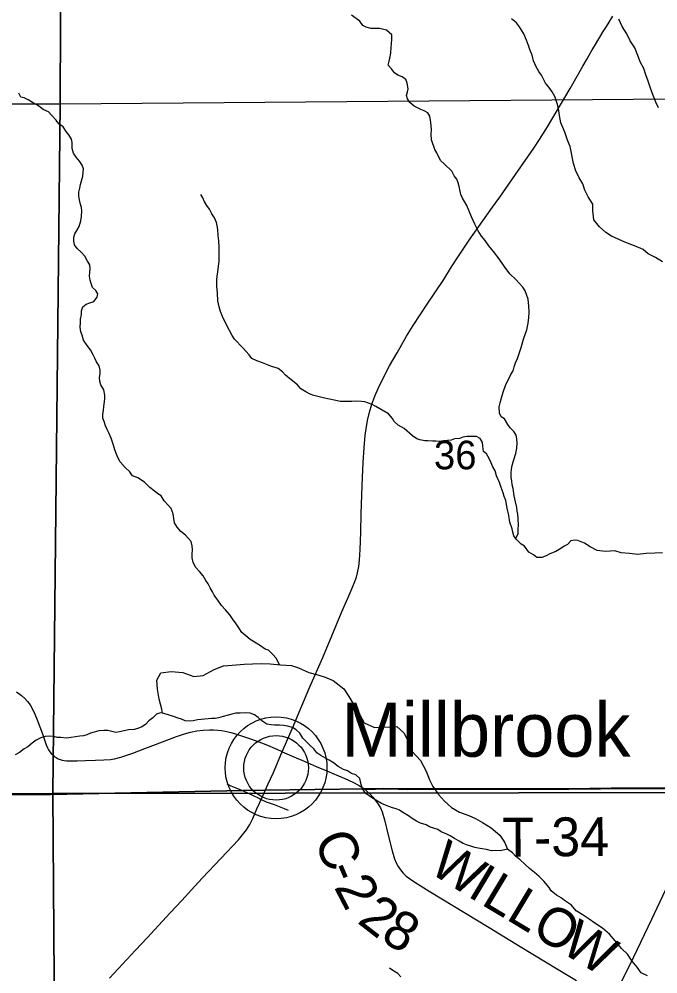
# Model space of a CAD drawing. Extents: x 0 to 34, y 0 to 22.
# Drawn here: x 4.694 to 5.628, y 15 to 16.396 of the extents above; entities that cross this region are included whole.
import ezdxf

# ---------------------------------------------------------------- set-up
doc = ezdxf.new("R2010")
doc.units = 0
for name, color, linetype in [('GM_X_County_Road', 7, 'Continuous'), ('GM_X_County_Road_Text', 7, 'Continuous'), ('GM_X_Minor_River', 7, 'Continuous'), ('GM_X_Section', 7, 'Continuous'), ('GM_X_Section_Text', 7, 'Continuous'), ('GM_X_State_Route', 7, 'Continuous'), ('GM_X_Township_Road', 7, 'Continuous'), ('GM_X_Township_Road_Text', 7, 'Continuous'), ('GM_X_Unincorporated', 7, 'Continuous'), ('GM_X_Unincorporated_Location', 7, 'Continuous'), ('GM_X_Unincorporated_Text', 7, 'Continuous')]:
    doc.layers.add(name, color=color, linetype=linetype)

msp = doc.modelspace()

# ---------------------------------------------------------------- linework, layer by layer
at = {"layer": 'GM_X_County_Road'}
msp.add_line((5.0478, 15.2549), (5.0536, 15.2677), dxfattribs=at)
for points in [[(5.0786, 15.3245), (5.0863, 15.3426), (5.0948, 15.3626), (5.1034, 15.3825), (5.119, 15.4195), (5.1376, 15.4624), (5.1512, 15.4939), (5.1653, 15.528), (5.1779, 15.5567), (5.1836, 15.5708), (5.1869, 15.5797), (5.1886, 15.586), (5.1903, 15.5953), (5.1914, 15.6046), (5.1923, 15.6201), (5.1932, 15.645), (5.194, 15.6729), (5.1954, 15.7132), (5.196, 15.7256), (5.1968, 15.7472), (5.198, 15.7689), (5.1999, 15.7874), (5.2011, 15.7966), (5.2033, 15.8088), (5.2062, 15.8208), (5.2096, 15.8327), (5.2138, 15.8443), (5.2186, 15.8557), (5.2254, 15.8696), (5.2355, 15.8888), (5.2463, 15.9077), (5.2603, 15.9318), (5.27, 15.9478), (5.2903, 15.9789), (5.3025, 15.997), (5.3146, 16.015), (5.3261, 16.0335), (5.3361, 16.0492), (5.3517, 16.0724), (5.3857, 16.1206), (5.3964, 16.1354), (5.4054, 16.148), (5.4196, 16.1684), (5.4461, 16.2067), (5.4545, 16.2197), (5.466, 16.2382), (5.485, 16.2702), (5.4994, 16.2942), (5.5181, 16.3265), (5.5241, 16.3373), (5.5271, 16.3426), (5.5316, 16.3506), (5.5347, 16.356), (5.5426, 16.3693), (5.5475, 16.3772), (5.5525, 16.3849), (5.5618, 16.4)], [(4.6902, 15.4122), (4.6975, 15.4066), (4.7021, 15.4025), (4.7063, 15.3981), (4.7099, 15.3932), (4.713, 15.3879), (4.717, 15.3796), (4.7204, 15.371), (4.7279, 15.3505), (4.7336, 15.3348), (4.7355, 15.3301), (4.737, 15.3273), (4.7387, 15.3246), (4.7407, 15.3221), (4.7429, 15.3198), (4.7453, 15.3177), (4.748, 15.3159), (4.7508, 15.3144), (4.7538, 15.3132), (4.7568, 15.3124), (4.7599, 15.3118), (4.7631, 15.3114), (4.7694, 15.3112), (4.7788, 15.3114), (4.7909, 15.3118), (4.8056, 15.312), (4.8179, 15.3125), (4.8273, 15.3134), (4.8335, 15.3144), (4.8426, 15.3165), (4.8486, 15.3184), (4.8602, 15.3227), (4.8776, 15.3294), (4.8891, 15.3338), (4.9239, 15.3469), (4.9357, 15.3508), (4.9446, 15.3532), (4.9536, 15.355), (4.9628, 15.3561), (4.9721, 15.3566), (4.9782, 15.3565), (4.9844, 15.3563), (4.9898, 15.3557), (4.9949, 15.3547), (4.9995, 15.3536), (5.0034, 15.3525), (5.0088, 15.351), (5.0203, 15.3475), (5.032, 15.3435), (5.0495, 15.3371), (5.0601, 15.3328), (5.0645, 15.3308), (5.0706, 15.3282), (5.0778, 15.3248), (5.0786, 15.3245)], [(5.0536, 15.2677), (5.0581, 15.2774), (5.0655, 15.2944), (5.0766, 15.3198), (5.0786, 15.3245)], [(5.0786, 15.3245), (5.0887, 15.3201), (5.0988, 15.3158), (5.1071, 15.3123), (5.1195, 15.3068), (5.128, 15.3032), (5.1365, 15.2994), (5.1425, 15.2969), (5.1513, 15.2932), (5.1702, 15.2853), (5.1816, 15.2801), (5.1909, 15.2751), (5.1951, 15.2725), (5.199, 15.2698)], [(5.199, 15.2698), (5.202, 15.2671), (5.2069, 15.2624), (5.211, 15.258), (5.215, 15.2532), (5.2187, 15.2481), (5.2204, 15.2455), (5.2219, 15.2426), (5.2243, 15.2368), (5.2278, 15.2248), (5.2339, 15.2007), (5.2392, 15.1796), (5.2428, 15.1678), (5.245, 15.1621), (5.2479, 15.1567), (5.2514, 15.1517), (5.2554, 15.147), (5.2598, 15.1429), (5.2647, 15.1391), (5.2723, 15.1339), (5.2934, 15.1208), (5.3811, 15.0675), (5.4262, 15.04), (5.4632, 15.0172), (5.4792, 15.0075), (5.5085, 14.99)], [(4.826, 14.9937), (4.8642, 15.0345), (4.8811, 15.0527), (4.9148, 15.0892), (4.9318, 15.1073), (4.9508, 15.1278), (4.9617, 15.1401), (4.9885, 15.1687), (5.0145, 15.1958), (5.0206, 15.2029), (5.0262, 15.2105), (5.0311, 15.2184), (5.0353, 15.2268), (5.0415, 15.241), (5.0452, 15.2495), (5.0478, 15.2549)]]:
    msp.add_lwpolyline(points, dxfattribs=at)
at = {"layer": 'GM_X_Minor_River'}
for points in [[(5.2426, 16.3169), (5.2381, 16.323), (5.2335, 16.3283), (5.2346, 16.334), (5.2357, 16.3386), (5.2372, 16.3458), (5.2376, 16.3546), (5.2383, 16.3595), (5.2387, 16.3663), (5.2387, 16.3724), (5.231, 16.3793), (5.2207, 16.3819), (5.2078, 16.3819), (5.2013, 16.3835), (5.1963, 16.3861), (5.1917, 16.3926), (5.1799, 16.4014)], [(5.5041, 16.1842), (5.5005, 16.2042), (5.4994, 16.2095), (5.4955, 16.2183), (5.4917, 16.2301), (5.4859, 16.2441), (5.484, 16.2544), (5.4824, 16.2647), (5.4805, 16.2719), (5.477, 16.2822), (5.4728, 16.2894), (5.4682, 16.2962), (5.4633, 16.3019), (5.4602, 16.3077), (5.4575, 16.3137), (5.4537, 16.3187), (5.4498, 16.3255), (5.4456, 16.3347), (5.4437, 16.343), (5.4406, 16.351), (5.4383, 16.3571), (5.4356, 16.3647), (5.4318, 16.3742), (5.4253, 16.3841), (5.4207, 16.3898), (5.4134, 16.3959)], [(5.6284, 16.2656), (5.6247, 16.2743), (5.6206, 16.2838), (5.6168, 16.2945), (5.6135, 16.3047), (5.6101, 16.3142), (5.6071, 16.3233), (5.6015, 16.3329), (5.5981, 16.3424), (5.594, 16.3534), (5.5872, 16.3637), (5.582, 16.3739), (5.5756, 16.3846), (5.5707, 16.3956)], [(5.4201, 15.6361), (5.4232, 15.6437), (5.4232, 15.6506), (5.4236, 15.6551), (5.4232, 15.6654), (5.4228, 15.6719), (5.422, 15.6764), (5.4212, 15.6818), (5.4193, 15.6897), (5.4174, 15.6985), (5.4158, 15.7091), (5.4147, 15.7145), (5.4139, 15.7206), (5.4131, 15.7255), (5.4131, 15.7316), (5.4135, 15.7377), (5.4146, 15.743), (5.4161, 15.7483), (5.4199, 15.7605), (5.4214, 15.7685), (5.4218, 15.7757), (5.4214, 15.7818), (5.4202, 15.7871), (5.4171, 15.7928), (5.4118, 15.7981), (5.4083, 15.8027), (5.4034, 15.8111), (5.3984, 15.8141), (5.3961, 15.8194), (5.3957, 15.8289), (5.3968, 15.8346), (5.3991, 15.8419), (5.4014, 15.8502), (5.4055, 15.8613), (5.4093, 15.8689), (5.4124, 15.8761), (5.4158, 15.8814), (5.4177, 15.8871), (5.4196, 15.8932), (5.4222, 15.8993), (5.4249, 15.9065), (5.4279, 15.9156), (5.4309, 15.9278), (5.434, 15.9358), (5.4359, 15.9415), (5.437, 15.946), (5.4378, 15.951), (5.4389, 15.9593), (5.4392, 15.9673), (5.4388, 15.9761), (5.4381, 15.986), (5.4338, 15.9985), (5.4304, 16.0038), (5.425, 16.0095), (5.4201, 16.0149), (5.4116, 16.0225), (5.404, 16.0328), (5.3956, 16.0449), (5.3871, 16.056), (5.3806, 16.0639), (5.3753, 16.0719), (5.3699, 16.0784), (5.3649, 16.086), (5.3599, 16.0959), (5.355, 16.1066), (5.3519, 16.1149), (5.3484, 16.1229), (5.345, 16.129), (5.3419, 16.1339), (5.3396, 16.1393), (5.3385, 16.1442), (5.3369, 16.1507), (5.3358, 16.1564), (5.3335, 16.1617), (5.33, 16.1666), (5.3262, 16.1731), (5.3151, 16.1841), (5.3101, 16.1883), (5.3074, 16.1937), (5.3044, 16.2001), (5.3013, 16.2047), (5.2967, 16.2191), (5.2963, 16.2275), (5.2967, 16.234), (5.2959, 16.2442), (5.2943, 16.2534), (5.2913, 16.2583), (5.2859, 16.2614), (5.2809, 16.2633), (5.276, 16.2659), (5.2714, 16.2682), (5.2649, 16.2735), (5.2614, 16.2789), (5.2603, 16.2838), (5.2618, 16.2891), (5.2625, 16.2937), (5.261, 16.3017), (5.2591, 16.3074), (5.2537, 16.3112), (5.2476, 16.3135), (5.2426, 16.3169)], [(4.7862, 16.1818), (4.7819, 16.1879), (4.777, 16.1936), (4.7735, 16.1997), (4.7716, 16.2065), (4.7716, 16.2149), (4.7704, 16.2198), (4.7666, 16.2263), (4.7624, 16.2312), (4.7582, 16.2381), (4.7517, 16.2426), (4.7482, 16.248), (4.7417, 16.2544), (4.7367, 16.2598), (4.7291, 16.2632), (4.7207, 16.2697), (4.7134, 16.2735), (4.7073, 16.2773), (4.7012, 16.2803), (4.6962, 16.2815), (4.6936, 16.2872)], [(4.952, 15.5938), (4.9482, 15.6014), (4.947, 15.6079), (4.947, 15.6132), (4.9474, 15.62), (4.947, 15.6257), (4.9451, 15.6318), (4.937, 15.6413), (4.9302, 15.6463), (4.9248, 15.6528), (4.921, 15.6592), (4.9202, 15.6653), (4.919, 15.6725), (4.916, 15.6801), (4.911, 15.6855), (4.906, 15.6912), (4.9014, 15.6984), (4.8964, 15.7014), (4.8911, 15.706), (4.885, 15.711), (4.8773, 15.7186), (4.8674, 15.725), (4.8597, 15.7277), (4.8555, 15.7338), (4.849, 15.7399), (4.8414, 15.7483), (4.8383, 15.7547), (4.836, 15.7597), (4.8337, 15.7661), (4.8318, 15.7726), (4.8283, 15.7829), (4.8252, 15.7905), (4.8226, 15.7958), (4.8203, 15.8011), (4.818, 15.8072), (4.816, 15.8122), (4.8164, 15.8179), (4.8172, 15.8232), (4.8175, 15.8293), (4.8187, 15.8361), (4.819, 15.841), (4.819, 15.846), (4.8175, 15.8536), (4.8132, 15.8608), (4.8117, 15.8661), (4.8113, 15.8715), (4.8124, 15.8768), (4.8124, 15.8825), (4.8109, 15.8886), (4.8071, 15.8947), (4.8044, 15.9), (4.8021, 15.9049), (4.7982, 15.9118), (4.7933, 15.9186), (4.7879, 15.9262), (4.786, 15.9335), (4.7841, 15.9384), (4.7833, 15.9453), (4.7836, 15.9517), (4.7836, 15.9567), (4.7848, 15.9639), (4.7851, 15.9692), (4.787, 15.9749), (4.792, 15.9787), (4.7973, 15.9806), (4.803, 15.9825), (4.808, 15.989), (4.8087, 15.9939), (4.8061, 15.9989), (4.8011, 16.0034), (4.7992, 16.0091), (4.7976, 16.0141), (4.7965, 16.0198), (4.7972, 16.0255), (4.7976, 16.0308), (4.7972, 16.0365), (4.7937, 16.0418), (4.7899, 16.0491), (4.7845, 16.0548), (4.7788, 16.0601), (4.775, 16.0654), (4.7738, 16.0708), (4.7738, 16.0765), (4.7753, 16.0814), (4.7784, 16.0867), (4.7814, 16.0924), (4.7841, 16.1004), (4.7852, 16.1069), (4.7855, 16.1152), (4.7848, 16.1202), (4.7832, 16.1263), (4.7821, 16.1312), (4.7813, 16.1365), (4.7813, 16.1426), (4.7824, 16.1483), (4.7835, 16.1536), (4.7851, 16.1593), (4.787, 16.1658), (4.7873, 16.1715), (4.7881, 16.1765), (4.7862, 16.1818)], [(5.6344, 16.0405), (5.6242, 16.047), (5.6136, 16.0524), (5.6061, 16.0589), (5.5936, 16.0642), (5.5793, 16.0692), (5.5695, 16.0738), (5.56, 16.0784), (5.5517, 16.0834), (5.5423, 16.0918), (5.534, 16.1021), (5.5326, 16.115), (5.5326, 16.1249), (5.5258, 16.1359), (5.5206, 16.1454), (5.518, 16.1545), (5.5127, 16.1633), (5.5078, 16.1736), (5.5041, 16.1842)], [(4.9864, 16.0619), (4.9856, 16.0714), (4.9848, 16.0794), (4.9844, 16.0877), (4.9833, 16.0935), (4.9825, 16.098), (4.9794, 16.1052), (4.9756, 16.1109), (4.9722, 16.1178), (4.9683, 16.1231), (4.9649, 16.1284), (4.9626, 16.1342), (4.9595, 16.1391)], [(5.5107, 15.6332), (5.5057, 15.6338), (5.5003, 15.6327), (5.4954, 15.6277), (5.4908, 15.6251), (5.4855, 15.6216), (5.4782, 15.6171), (5.4698, 15.6137), (5.4641, 15.611), (5.4577, 15.6087), (5.4504, 15.6087), (5.4458, 15.6122), (5.4389, 15.6163), (5.4324, 15.6251), (5.4278, 15.6278), (5.4206, 15.6354), (5.4171, 15.6403), (5.4156, 15.6453), (5.4144, 15.6506), (5.4114, 15.6601), (5.4098, 15.67), (5.4071, 15.6806), (5.4052, 15.6917), (5.4029, 15.6977), (5.4013, 15.7031), (5.3983, 15.7107), (5.3959, 15.7183), (5.3917, 15.7278), (5.3898, 15.7354), (5.3864, 15.7411), (5.3833, 15.7476), (5.381, 15.7533), (5.3772, 15.7601), (5.3726, 15.7635), (5.3718, 15.7712), (5.371, 15.7765), (5.3679, 15.7822), (5.3626, 15.7852), (5.3481, 15.7852), (5.3427, 15.7845), (5.3374, 15.7826), (5.3305, 15.7818), (5.3252, 15.7799), (5.3141, 15.7788), (5.3084, 15.778), (5.3031, 15.7784), (5.2985, 15.7784), (5.2912, 15.7788), (5.2867, 15.7792), (5.2798, 15.7803), (5.2752, 15.7819), (5.2691, 15.7864), (5.2568, 15.7971), (5.2481, 15.802), (5.2423, 15.8073), (5.2396, 15.8119), (5.2339, 15.8184), (5.2243, 15.8237), (5.2152, 15.829), (5.2098, 15.8321), (5.1991, 15.8359), (5.1942, 15.8367), (5.1858, 15.837), (5.1804, 15.8367), (5.1759, 15.8363), (5.1705, 15.8363), (5.1633, 15.8367), (5.1568, 15.8378), (5.1381, 15.842), (5.1247, 15.8451), (5.1193, 15.847), (5.1132, 15.8508), (5.1056, 15.855), (5.1006, 15.8607), (5.0914, 15.8683), (5.0834, 15.8751), (5.0788, 15.8797), (5.0727, 15.8846), (5.062, 15.8881), (5.0544, 15.8911), (5.0498, 15.893), (5.0414, 15.8961), (5.0341, 15.8995), (5.0303, 15.9048), (5.0207, 15.9151), (5.0085, 15.9276), (5.0054, 15.933), (4.9974, 15.9474), (4.9912, 15.9607), (4.9882, 15.9683), (4.9862, 15.9748), (4.9843, 15.9836), (4.9839, 15.995), (4.9827, 16.0052), (4.9831, 16.0144), (4.9835, 16.0197), (4.9842, 16.0261), (4.9853, 16.0345), (4.9861, 16.0414), (4.9864, 16.0474), (4.9864, 16.0619)], [(5.6343, 15.6152), (5.6229, 15.6148), (5.6104, 15.6141), (5.5983, 15.6127), (5.5859, 15.6143), (5.5741, 15.6155), (5.5647, 15.6182), (5.5511, 15.6171), (5.539, 15.6187), (5.5284, 15.624), (5.5201, 15.6294), (5.5107, 15.6332)], [(5.0745, 15.4516), (5.0703, 15.4606), (5.0641, 15.4671), (5.0584, 15.4728), (5.0534, 15.4743), (5.0454, 15.4804), (5.0317, 15.4888), (5.0252, 15.4938), (5.0194, 15.4987), (5.0148, 15.5059), (5.011, 15.5113), (5.0056, 15.5189), (5.0018, 15.5249), (4.9953, 15.5318), (4.9896, 15.5383), (4.9842, 15.5459), (4.9792, 15.5535), (4.9765, 15.5584), (4.9731, 15.5641), (4.97, 15.5698), (4.967, 15.5748), (4.9631, 15.5816), (4.9574, 15.5881), (4.952, 15.5938)], [(4.9033, 15.3809), (4.9025, 15.3867), (4.8987, 15.4015), (4.896, 15.4159), (4.8951, 15.4292), (4.9008, 15.4399), (4.9163, 15.4418), (4.9334, 15.4403), (4.9493, 15.4347), (4.9629, 15.4359), (4.9788, 15.445), (4.9928, 15.45), (5.0053, 15.4512), (5.0227, 15.4524), (5.0352, 15.4532), (5.0485, 15.4536), (5.061, 15.4529), (5.0761, 15.4514), (5.092, 15.4504), (5.1023, 15.4474), (5.1174, 15.4402), (5.1307, 15.4372), (5.141, 15.4334), (5.1527, 15.4285), (5.1687, 15.4164), (5.1759, 15.4055), (5.1831, 15.3933), (5.1896, 15.3827), (5.1984, 15.3668), (5.2132, 15.36), (5.2261, 15.3608), (5.2363, 15.3605), (5.2461, 15.3613), (5.256, 15.3522), (5.2644, 15.3363), (5.2686, 15.3249), (5.2804, 15.3117), (5.2888, 15.2962), (5.2938, 15.2833), (5.2984, 15.2738), (5.3068, 15.2621), (5.3159, 15.2522), (5.3258, 15.2428), (5.3375, 15.2363), (5.3512, 15.2311), (5.361, 15.2269), (5.3713, 15.2209), (5.3838, 15.2133), (5.3967, 15.2024), (5.4032, 15.1925), (5.4077, 15.1823)], [(5.4077, 15.1823), (5.3968, 15.1798), (5.3904, 15.1802), (5.3842, 15.1795), (5.377, 15.1817), (5.3709, 15.1825), (5.3648, 15.1837), (5.3598, 15.1848), (5.3541, 15.1863), (5.348, 15.1886), (5.343, 15.1905), (5.3373, 15.1936), (5.3304, 15.1977), (5.3239, 15.2015), (5.3189, 15.2042), (5.3109, 15.2076), (5.3059, 15.2107), (5.2998, 15.213), (5.2937, 15.2149), (5.2888, 15.2175), (5.2807, 15.2202), (5.2746, 15.2229), (5.2685, 15.2271), (5.2632, 15.2309), (5.2547, 15.2358), (5.2498, 15.2389), (5.2448, 15.2411), (5.2395, 15.2427), (5.2341, 15.2446), (5.2292, 15.2465), (5.2234, 15.2488), (5.2154, 15.2537), (5.2089, 15.2575), (5.2009, 15.2636), (5.1959, 15.2704), (5.194, 15.2765), (5.1917, 15.2853), (5.1859, 15.2906), (5.1798, 15.2929), (5.1741, 15.2967), (5.168, 15.2986), (5.1603, 15.3032), (5.1534, 15.3081), (5.1473, 15.3123), (5.1416, 15.3153), (5.1347, 15.3192), (5.129, 15.323), (5.1248, 15.3287), (5.119, 15.334), (5.1137, 15.3389), (5.1087, 15.3446), (5.1041, 15.3515), (5.0988, 15.3568), (5.0934, 15.3602), (5.0861, 15.3618), (5.0804, 15.3629), (5.0743, 15.3633), (5.0674, 15.3633), (5.0625, 15.3637), (5.056, 15.3648), (5.0487, 15.3698), (5.0434, 15.3747), (5.038, 15.3785), (5.0315, 15.3808), (5.0243, 15.3812), (5.017, 15.3808), (5.0105, 15.3808), (5.0048, 15.3793), (4.9995, 15.3782), (4.9922, 15.3759), (4.9854, 15.374), (4.9804, 15.3729), (4.9751, 15.3729), (4.9602, 15.3717), (4.9545, 15.371), (4.9484, 15.3698), (4.9423, 15.3691), (4.9365, 15.3698), (4.9312, 15.3721), (4.9262, 15.3736), (4.9197, 15.3763), (4.9117, 15.3786), (4.9056, 15.3805), (4.9006, 15.3813), (4.8945, 15.3797), (4.8892, 15.374), (4.8835, 15.3695), (4.8785, 15.3642), (4.8732, 15.3611), (4.8675, 15.3585), (4.8621, 15.357), (4.8538, 15.3566), (4.8473, 15.3551), (4.8404, 15.3535), (4.8351, 15.3528), (4.8293, 15.3539), (4.8236, 15.3555), (4.8179, 15.3555), (4.8106, 15.3551), (4.8034, 15.3532), (4.7984, 15.3517)], [(4.7984, 15.3517), (4.7927, 15.3494), (4.7878, 15.3479), (4.7828, 15.3475), (4.7698, 15.3456), (4.7633, 15.3445), (4.7546, 15.3456), (4.7496, 15.3456), (4.7446, 15.3467), (4.7378, 15.3471), (4.732, 15.3468), (4.7256, 15.3449), (4.7187, 15.3414), (4.713, 15.3373), (4.7065, 15.3319), (4.7012, 15.3289), (4.6943, 15.3236), (4.6882, 15.3198)], [(5.5079, 15.0921), (5.5012, 15.1003), (5.4913, 15.1071), (5.4863, 15.111), (5.4794, 15.1151), (5.4718, 15.1212), (5.4687, 15.1262), (5.4611, 15.1353), (5.4538, 15.1422), (5.4473, 15.1479), (5.44, 15.1539), (5.4331, 15.1604), (5.4259, 15.1669), (5.4201, 15.1715), (5.4152, 15.1768), (5.4077, 15.1823)], [(5.6126, 14.9969), (5.6031, 15.0015), (5.5974, 15.0098), (5.5902, 15.0186), (5.583, 15.0285), (5.5743, 15.0369), (5.5652, 15.0483), (5.5568, 15.0578), (5.5466, 15.0666), (5.5356, 15.0742), (5.5269, 15.0799), (5.5167, 15.0864), (5.5079, 15.0921)], [(5.2519, 14.9955), (5.2473, 15.0004), (5.2416, 15.0039), (5.2354, 15.008)]]:
    msp.add_lwpolyline(points, dxfattribs=at)
at = {"layer": 'GM_X_Section'}
for points in [[(4.7564, 16.8709), (4.754, 16.2718), (5.7718, 16.2797), (5.7724, 17.2281), (5.7727, 17.3042), (4.804, 17.2765), (4.804, 16.8709)], [(3.7435, 16.8709), (3.7413, 16.2718), (4.754, 16.2718), (4.7564, 16.8709)], [(5.7718, 16.2797), (5.7699, 16.2149), (5.7637, 15.2651), (4.743, 15.2637), (4.754, 16.2718)], [(3.7413, 16.2718), (4.754, 16.2718), (4.743, 15.2637), (3.7425, 15.2596), (3.7269, 15.2595)], [(3.7425, 15.2596), (4.743, 15.2637), (4.7506, 14.2503), (4.2965, 14.2473), (3.7447, 14.2621)], [(5.7637, 15.2651), (5.7673, 14.2653), (4.7506, 14.2503), (4.743, 15.2637)]]:
    msp.add_lwpolyline(points, close=True, dxfattribs=at)
at = {"layer": 'GM_X_State_Route'}
msp.add_lwpolyline([(5.5686, 14.9763), (5.592, 15.0236), (5.6188, 15.0798), (5.6385, 15.1221), (5.6937, 15.2404), (5.7075, 15.2708)], dxfattribs=at)
at = {"layer": 'GM_X_Township_Road'}
for points in [[(4.6902, 15.4122), (4.6975, 15.4066), (4.7021, 15.4025), (4.7063, 15.3981), (4.7099, 15.3932), (4.713, 15.3879), (4.717, 15.3796), (4.7204, 15.371), (4.7279, 15.3505), (4.7336, 15.3348), (4.7355, 15.3301), (4.737, 15.3273), (4.7387, 15.3246), (4.7407, 15.3221), (4.7429, 15.3198), (4.7453, 15.3177), (4.748, 15.3159), (4.7508, 15.3144), (4.7538, 15.3132), (4.7568, 15.3124), (4.7599, 15.3118), (4.7631, 15.3114), (4.7694, 15.3112), (4.7788, 15.3114), (4.7909, 15.3118), (4.8056, 15.312), (4.8179, 15.3125), (4.8273, 15.3134), (4.8335, 15.3144), (4.8426, 15.3165), (4.8486, 15.3184), (4.8602, 15.3227), (4.8776, 15.3294), (4.8891, 15.3338), (4.9239, 15.3469), (4.9357, 15.3508), (4.9446, 15.3532), (4.9536, 15.355), (4.9628, 15.3561), (4.9721, 15.3566), (4.9782, 15.3565), (4.9844, 15.3563), (4.9898, 15.3557), (4.9949, 15.3547), (4.9995, 15.3536), (5.0034, 15.3525), (5.0088, 15.351), (5.0203, 15.3475), (5.032, 15.3435), (5.0495, 15.3371), (5.0601, 15.3328), (5.0645, 15.3308), (5.0706, 15.3282), (5.0778, 15.3248), (5.0786, 15.3245)], [(5.0786, 15.3245), (5.0887, 15.3201), (5.0988, 15.3158), (5.1071, 15.3123), (5.1195, 15.3068), (5.128, 15.3032), (5.1365, 15.2994), (5.1425, 15.2969), (5.1513, 15.2932), (5.1702, 15.2853), (5.1816, 15.2801), (5.1909, 15.2751), (5.1951, 15.2725), (5.199, 15.2698)], [(5.643, 15.2716), (5.6119, 15.2714), (5.5902, 15.2714), (5.5592, 15.2712), (5.5436, 15.271), (5.5281, 15.2708), (5.4971, 15.2705), (5.4691, 15.2704), (5.3852, 15.2701), (5.3448, 15.2702), (5.3027, 15.2702), (5.2613, 15.2701), (5.2481, 15.2703), (5.2267, 15.2706), (5.2145, 15.2705), (5.2045, 15.2703), (5.1988, 15.2703), (5.0534, 15.2682), (5.0211, 15.2677), (4.7402, 15.2622), (3.727, 15.2572)], [(3.727, 15.2572), (4.7402, 15.2622), (5.0211, 15.2677), (5.0534, 15.2682), (5.1988, 15.2703), (5.2045, 15.2703), (5.2145, 15.2705), (5.2267, 15.2706), (5.2481, 15.2703), (5.2613, 15.2701), (5.3027, 15.2702), (5.3448, 15.2702), (5.3852, 15.2701), (5.4691, 15.2704), (5.4971, 15.2705), (5.5281, 15.2708), (5.5436, 15.271), (5.5592, 15.2712), (5.5902, 15.2714), (5.6119, 15.2714), (5.643, 15.2716)], [(4.9974, 15.2775), (5.0035, 15.2748), (5.0108, 15.2717), (5.0213, 15.2672)], [(5.199, 15.2698), (5.2047, 15.2697), (5.2147, 15.27), (5.2269, 15.2701), (5.2483, 15.2698), (5.2615, 15.2695), (5.3029, 15.2696), (5.345, 15.2696), (5.3854, 15.2696), (5.4693, 15.2699), (5.4973, 15.27), (5.5283, 15.2703), (5.5439, 15.2704), (5.5594, 15.2706), (5.5904, 15.2708), (5.6121, 15.2708), (5.6432, 15.271), (5.6867, 15.2712), (5.7075, 15.2708)], [(5.0213, 15.2672), (5.0348, 15.261), (5.0451, 15.2564), (5.0478, 15.2549)], [(5.0478, 15.2549), (5.0548, 15.2515), (5.0667, 15.2473), (5.0815, 15.2418), (5.0873, 15.2393)]]:
    msp.add_lwpolyline(points, dxfattribs=at)
at = {"layer": 'GM_X_Unincorporated'}
for radius in [0.0744, 0.0472]:
    msp.add_circle((5.0695, 15.301), radius, dxfattribs=at)
at = {"layer": 'GM_X_Unincorporated_Location'}
msp.add_line((5.0695, 15.301), (5.0695, 15.301), dxfattribs=at)

# ---------------------------------------------------------------- texts
at = {"layer": 'GM_X_County_Road_Text'}
for s, rotation, p in [('C', 292.8245, (5.1241, 15.1959)), ('W', 328.0939, (5.2908, 15.1496)), ('-', 293.1779, (5.1423, 15.1525)), ('I', 329.0475, (5.3476, 15.1142)), ('2', 297.3879, (5.1535, 15.1269)), ('L', 329.0359, (5.3676, 15.1022)), ('L', 329.034, (5.404, 15.0804)), ('2', 322.208, (5.1866, 15.0754)), ('8', 328.8621, (5.2202, 15.0498)), ('O', 329.0352, (5.4405, 15.0585)), ('W', 329.0346, (5.4834, 15.0328))]:
    msp.add_text(s, height=0.0568, rotation=rotation, dxfattribs=at).set_placement(p)
at = {"layer": 'GM_X_Section_Text'}
msp.add_text('36', height=0.04186, rotation=0, dxfattribs=at).set_placement((5.3002, 15.7374))
at = {"layer": 'GM_X_Township_Road_Text'}
msp.add_text('T-34', height=0.05682, rotation=0.3553, dxfattribs=at).set_placement((5.4002, 15.1712))
at = {"layer": 'GM_X_Unincorporated_Text'}
msp.add_text('Millbrook', height=0.07898, rotation=0, dxfattribs=at).set_placement((5.1652, 15.3173))

doc.saveas('drawing.dxf')
